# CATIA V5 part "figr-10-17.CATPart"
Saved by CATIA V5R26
Part number: Part1
Bounding box of the stored display mesh (mm): x -29.811 to 29.811, y 0 to 29.811, z -21.213 to 21.213
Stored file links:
  D:\_Deepak\CATIA\CATIA V5-6R2016_Deepak\Resources\Part files\Partfiles\c10_catia_v5_6r2016_prt\figr-10-17.CATPart
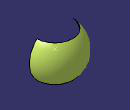
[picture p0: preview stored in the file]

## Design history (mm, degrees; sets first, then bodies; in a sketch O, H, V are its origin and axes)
Set1
  Point1: (0, 0, 0)
  Sphere1: Center Point1, Radius 30, Para1 -45, Para3 0, Para4 180
Body1 (main body)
